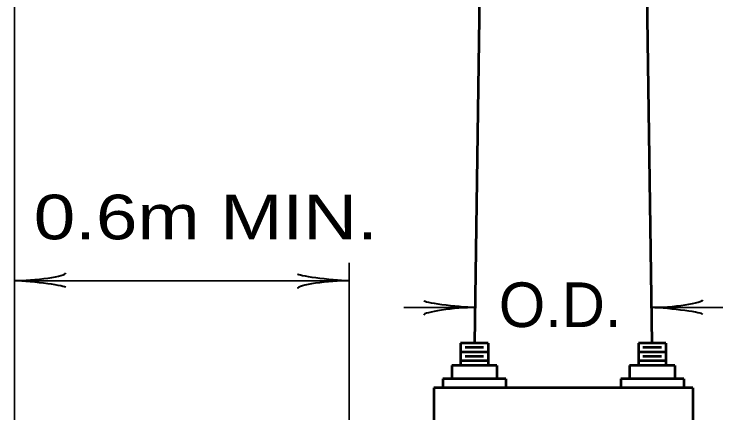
# Model space of a CAD drawing. Extents: x -34 to 822, y -23 to 521.
# Drawn here: x 528.64 to 576.27, y 260.75 to 287.57 of the extents above; entities that cross this region are included whole.
import ezdxf
from ezdxf.enums import TextEntityAlignment as Align

# ---------------------------------------------------------------- set-up
doc = ezdxf.new("R2010")
doc.units = 0
doc.header["$LTSCALE"] = 1.2
doc.layers.add('1', color=7, linetype='Continuous', lineweight=35)

msp = doc.modelspace()

# ---------------------------------------------------------------- linework, layer by layer
at = {"layer": '1', "lineweight": 53}
for p, q in [((561.663, 411.49), (559.59, 265.442)), ((569.431, 411.529), (571.505, 265.442)), ((560.49, 265.442), (558.648, 265.442)), ((558.648, 265.442), (558.648, 263.942)), ((560.49, 265.442), (560.49, 263.942)), ((572.448, 265.442), (570.605, 265.442)), ((570.605, 265.442), (570.605, 263.942)), ((572.448, 265.442), (572.448, 263.942)), ((560.19, 265.142), (558.948, 265.142)), ((572.148, 265.142), (570.905, 265.142)), ((560.49, 264.842), (558.648, 264.842)), ((560.19, 264.542), (558.948, 264.542)), ((572.448, 264.842), (570.605, 264.842)), ((572.148, 264.542), (570.905, 264.542)), ((561.09, 263.942), (558.048, 263.942)), ((558.048, 263.942), (558.048, 263.042)), ((560.49, 264.242), (558.648, 264.242)), ((561.09, 263.942), (561.09, 263.042)), ((573.048, 263.942), (570.005, 263.942)), ((570.005, 263.942), (570.005, 263.042)), ((572.448, 264.242), (570.605, 264.242)), ((573.048, 263.942), (573.048, 263.042)), ((561.69, 263.042), (557.448, 263.042)), ((557.448, 263.042), (557.448, 262.442)), ((561.69, 263.042), (561.69, 262.442)), ((573.648, 263.042), (569.405, 263.042)), ((569.405, 263.042), (569.405, 262.442)), ((573.648, 263.042), (573.648, 262.442)), ((574.248, 262.442), (556.848, 262.442)), ((556.848, 262.442), (556.848, 260.042)), ((574.248, 262.442), (574.248, 260.042))]:
    msp.add_line(p, q, dxfattribs=at)
at = {"layer": '1'}
for p, q in [((528.648, 253.142), (528.648, 305.942)), ((551.148, 258.193), (551.148, 270.842)), ((551.148, 269.642), (528.648, 269.642)), ((559.624, 267.841), (554.824, 267.841)), ((571.471, 267.841), (576.271, 267.841))]:
    msp.add_line(p, q, dxfattribs=at)
at = {"layer": '1', "lineweight": 40}
for centre, major_axis, ratio, start_param, end_param in [((529.957, 269.973), (-2.143, -0.187), 0.122415, 0.896353, 3.141593), ((529.957, 269.973), (-2.143, -0.187), 0.122415, 0.896353, 3.141593), ((549.803, 269.896), (2.108, -0.211), 0.07063, 3.140715, 5.41811), ((549.803, 269.896), (2.108, -0.211), 0.07063, 3.140715, 5.41811), ((529.992, 269.388), (-2.108, 0.211), 0.07063, 3.140715, 5.41811), ((529.992, 269.388), (-2.108, 0.211), 0.07063, 3.140715, 5.41811), ((549.838, 269.31), (2.143, 0.187), 0.122415, 0.896353, 3.141593), ((549.838, 269.31), (2.143, 0.187), 0.122415, 0.896353, 3.141593), ((558.28, 268.095), (2.108, -0.211), 0.07063, 3.140715, 5.41811), ((558.28, 268.095), (2.108, -0.211), 0.07063, 3.140715, 5.41811), ((572.781, 268.173), (-2.143, -0.187), 0.122415, 0.896353, 3.141593), ((558.315, 267.51), (2.143, 0.187), 0.122415, 0.896353, 3.141593), ((558.315, 267.51), (2.143, 0.187), 0.122415, 0.896353, 3.141593), ((572.816, 267.588), (-2.108, 0.211), 0.07063, 3.140715, 5.41811)]:
    msp.add_ellipse(centre, major_axis=major_axis, ratio=ratio, start_param=start_param, end_param=end_param, dxfattribs=at)

# ---------------------------------------------------------------- texts
at = {"layer": '1', "width": 1.25}
msp.add_text('0.6m MIN.', height=3, dxfattribs=at).set_placement((541.515, 272.426), align=Align.CENTER)
at = {"layer": '1'}
msp.add_text('O.D.', height=3, dxfattribs=at).set_placement((565.337, 266.525), align=Align.CENTER)

doc.saveas('drawing.dxf')
